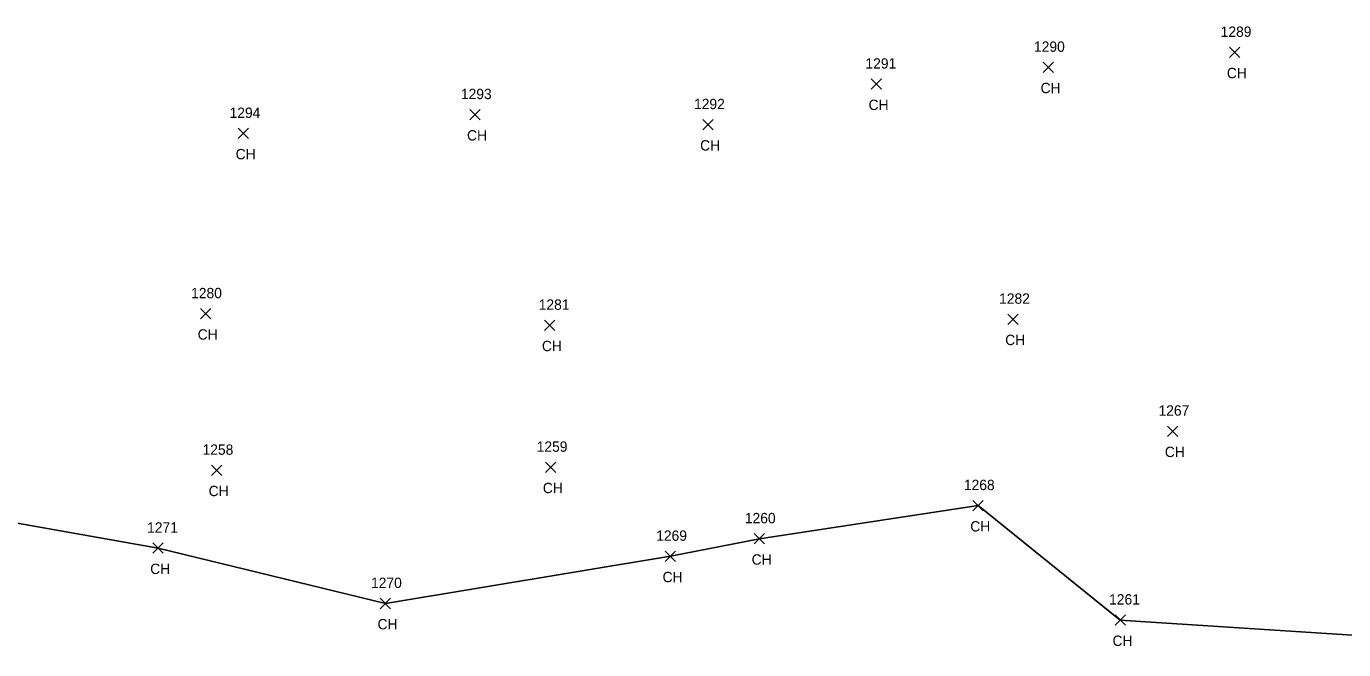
# Model space of a CAD drawing. Extents: x 1715662 to 1717487, y 887396 to 890004.
# Drawn here: x 1717104.2 to 1717358.8, y 888067 to 888187.5 of the extents above; entities that cross this region are included whole.
import ezdxf

# ---------------------------------------------------------------- set-up
doc = ezdxf.new("R2010")
doc.units = 0
for name, color, linetype in [('L_A', 7, 'Continuous'), ('L_I', 7, 'Continuous'), ('L_TIC', 7, 'Continuous'), ('LSOGP', 7, 'Continuous')]:
    doc.layers.add(name, color=color, linetype=linetype)

msp = doc.modelspace()

# ---------------------------------------------------------------- linework, layer by layer
at = {"layer": 'L_TIC'}
for points in [[(1717336.74, 888181.47), (1717338.74, 888183.47)], [(1717338.74, 888181.47), (1717336.74, 888183.47)], [(1717300.74, 888178.58), (1717302.74, 888180.58)], [(1717302.74, 888178.58), (1717300.74, 888180.58)], [(1717267.5, 888175.33), (1717269.5, 888177.33)], [(1717269.5, 888175.33), (1717267.5, 888177.33)], [(1717189.89, 888169.43), (1717191.89, 888171.43)], [(1717191.89, 888169.43), (1717189.89, 888171.43)], [(1717145.17, 888165.8), (1717147.17, 888167.8)], [(1717147.17, 888165.8), (1717145.17, 888167.8)], [(1717234.95, 888167.49), (1717236.95, 888169.49)], [(1717236.95, 888167.49), (1717234.95, 888169.49)], [(1717137.83, 888130.94), (1717139.83, 888132.94)], [(1717139.83, 888130.94), (1717137.83, 888132.94)], [(1717293.9, 888129.88), (1717295.9, 888131.88)], [(1717295.9, 888129.88), (1717293.9, 888131.88)], [(1717204.36, 888128.71), (1717206.36, 888130.71)], [(1717206.36, 888128.71), (1717204.36, 888130.71)], [(1717324.76, 888108.24), (1717326.76, 888110.24)], [(1717326.76, 888108.24), (1717324.76, 888110.24)], [(1717139.96, 888100.68), (1717141.96, 888102.68)], [(1717141.96, 888100.68), (1717139.96, 888102.68)], [(1717204.54, 888101.26), (1717206.54, 888103.26)], [(1717206.54, 888101.26), (1717204.54, 888103.26)], [(1717287.15, 888093.85), (1717289.15, 888095.85)], [(1717289.15, 888093.85), (1717287.15, 888095.85)], [(1717244.9, 888087.44), (1717246.9, 888089.44)], [(1717246.9, 888087.44), (1717244.9, 888089.44)], [(1717128.67, 888085.63), (1717130.67, 888087.63)], [(1717130.67, 888085.63), (1717128.67, 888087.63)], [(1717227.68, 888084.05), (1717229.68, 888086.05)], [(1717229.68, 888084.05), (1717227.68, 888086.05)], [(1717172.6, 888074.93), (1717174.6, 888076.93)], [(1717174.6, 888074.93), (1717172.6, 888076.93)], [(1717314.64, 888071.73), (1717316.64, 888073.73)], [(1717316.64, 888071.73), (1717314.64, 888073.73)]]:
    msp.add_lwpolyline(points, dxfattribs=at)
at = {"layer": 'LSOGP'}
msp.add_lwpolyline([(1717086.78, 888094.24), (1717129.67, 888086.63), (1717173.6, 888075.93), (1717228.68, 888085.05), (1717245.9, 888088.44), (1717288.15, 888094.85), (1717315.64, 888072.73), (1717403.35, 888067.01)], dxfattribs=at)

# ---------------------------------------------------------------- texts
at = {"layer": 'L_A'}
for p in [(1717336.23, 888177.47), (1717300.23, 888174.58), (1717266.99, 888171.33), (1717189.38, 888165.43), (1717234.43, 888163.49), (1717144.66, 888161.8), (1717137.32, 888126.94), (1717293.39, 888125.88), (1717203.85, 888124.71), (1717324.25, 888104.24), (1717204.03, 888097.26), (1717139.44, 888096.68), (1717286.64, 888089.85), (1717128.15, 888081.63), (1717244.39, 888083.44), (1717227.17, 888080.05), (1717172.09, 888070.93), (1717314.13, 888067.73)]:
    msp.add_text('CH', height=2, dxfattribs=at).set_placement(p)
at = {"layer": 'L_I'}
for s, p in [('1289', (1717335.04, 888185.47)), ('1290', (1717298.96, 888182.58)), ('1291', (1717266.38, 888179.33)), ('1293', (1717188.19, 888173.43)), ('1292', (1717233.25, 888171.49)), ('1294', (1717143.48, 888169.8)), ('1280', (1717136.05, 888134.94)), ('1281', (1717203.23, 888132.71)), ('1282', (1717292.21, 888133.88)), ('1267', (1717323.02, 888112.24)), ('1258', (1717138.26, 888104.68)), ('1259', (1717202.84, 888105.26)), ('1268', (1717285.41, 888097.85)), ('1271', (1717127.54, 888089.63)), ('1260', (1717243.07, 888091.44)), ('1269', (1717225.93, 888088.05)), ('1270', (1717170.82, 888078.93)), ('1261', (1717313.47, 888075.73))]:
    msp.add_text(s, height=2, dxfattribs=at).set_placement(p)

doc.saveas('drawing.dxf')
